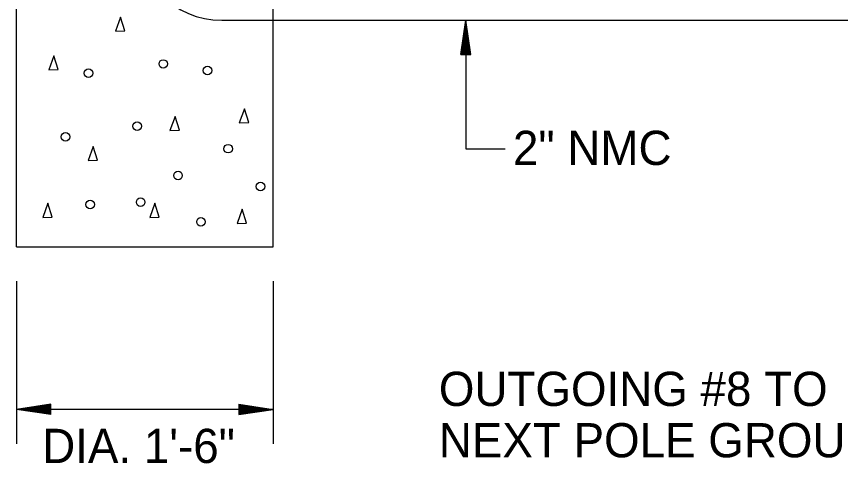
# Model space of a CAD drawing. Extents: x 1370050 to 1370716, y 380076 to 380502.
# Drawn here: x 1370124.1 to 1370196.4, y 380323.6 to 380362.8 of the extents above; entities that cross this region are included whole.
import ezdxf

# ---------------------------------------------------------------- set-up
doc = ezdxf.new("R2010")
doc.units = 0
doc.layers.add('R_Grid', color=7, linetype='Continuous')

msp = doc.modelspace()

# ---------------------------------------------------------------- linework, layer by layer
at = {"layer": 'R_Grid'}
for p, q in [((1370124.106, 380342.578), (1370124.106, 380387.578)), ((1370146.606, 380342.578), (1370146.606, 380387.578)), ((1370142.106, 380362.44), (1370216.311, 380362.44)), ((1370163.07, 380359.44), (1370163.52, 380362.44)), ((1370163.52, 380362.44), (1370163.52, 380351.167)), ((1370163.97, 380359.44), (1370163.52, 380362.44)), ((1370163.145, 380359.44), (1370163.52, 380361.939)), ((1370163.895, 380359.44), (1370163.52, 380361.939)), ((1370163.221, 380359.44), (1370163.52, 380361.423)), ((1370163.818, 380359.44), (1370163.52, 380361.423)), ((1370163.296, 380359.44), (1370163.52, 380360.924)), ((1370163.374, 380359.44), (1370163.52, 380360.415)), ((1370163.743, 380359.44), (1370163.52, 380360.924)), ((1370163.667, 380359.44), (1370163.52, 380360.415)), ((1370163.449, 380359.44), (1370163.52, 380359.914)), ((1370163.59, 380359.44), (1370163.52, 380359.914)), ((1370163.07, 380359.44), (1370163.97, 380359.44)), ((1370163.52, 380351.167), (1370166.976, 380351.167)), ((1370124.106, 380342.578), (1370146.606, 380342.578)), ((1370124.106, 380339.578), (1370124.106, 380325.328)), ((1370146.606, 380339.578), (1370146.606, 380325.328)), ((1370127.106, 380328.778), (1370124.106, 380328.328)), ((1370127.106, 380328.703), (1370124.607, 380328.328)), ((1370127.106, 380328.626), (1370125.123, 380328.328)), ((1370127.106, 380328.551), (1370125.623, 380328.328)), ((1370127.106, 380328.475), (1370126.131, 380328.328)), ((1370127.106, 380327.878), (1370127.106, 380328.778)), ((1370143.606, 380328.778), (1370146.606, 380328.328)), ((1370143.606, 380328.778), (1370143.606, 380327.878)), ((1370143.606, 380328.703), (1370146.105, 380328.328)), ((1370143.606, 380328.626), (1370145.589, 380328.328)), ((1370143.606, 380328.551), (1370145.09, 380328.328)), ((1370143.606, 380328.473), (1370144.581, 380328.328)), ((1370146.606, 380328.328), (1370124.106, 380328.328)), ((1370127.106, 380327.878), (1370124.106, 380328.328)), ((1370127.106, 380327.953), (1370124.607, 380328.328)), ((1370127.106, 380328.029), (1370125.123, 380328.328)), ((1370127.106, 380328.104), (1370125.623, 380328.328)), ((1370127.106, 380328.182), (1370126.131, 380328.328)), ((1370127.106, 380328.398), (1370126.632, 380328.328)), ((1370127.106, 380328.257), (1370126.632, 380328.328)), ((1370143.606, 380328.398), (1370144.08, 380328.328)), ((1370143.606, 380327.878), (1370146.606, 380328.328)), ((1370143.606, 380328.181), (1370144.581, 380328.328)), ((1370143.606, 380328.029), (1370145.589, 380328.328)), ((1370143.606, 380327.953), (1370146.105, 380328.328)), ((1370143.606, 380328.104), (1370145.09, 380328.328)), ((1370143.606, 380328.257), (1370144.08, 380328.328))]:
    msp.add_line(p, q, dxfattribs=at)
for points in [[(1370133.236, 380362.719), (1370132.783, 380361.474), (1370133.608, 380361.508), (1370133.236, 380362.719)], [(1370127.391, 380359.333), (1370126.937, 380358.088), (1370127.762, 380358.122), (1370127.391, 380359.333)], [(1370144.104, 380354.686), (1370143.65, 380353.441), (1370144.475, 380353.475), (1370144.104, 380354.686)], [(1370138.022, 380354.015), (1370137.568, 380352.77), (1370138.393, 380352.804), (1370138.022, 380354.015)], [(1370130.839, 380351.38), (1370130.385, 380350.135), (1370131.21, 380350.169), (1370130.839, 380351.38)], [(1370126.864, 380346.398), (1370126.411, 380345.153), (1370127.236, 380345.186), (1370126.864, 380346.398)], [(1370136.25, 380346.398), (1370135.796, 380345.153), (1370136.621, 380345.186), (1370136.25, 380346.398)], [(1370143.912, 380345.871), (1370143.458, 380344.626), (1370144.283, 380344.659), (1370143.912, 380345.871)]]:
    msp.add_lwpolyline(points, dxfattribs=at)
for centre in [(1370136.982, 380358.608), (1370130.428, 380357.807), (1370140.861, 380358.033), (1370134.684, 380353.147), (1370128.404, 380352.223), (1370142.681, 380351.182), (1370138.275, 380348.835), (1370145.506, 380347.877), (1370130.565, 380346.296), (1370134.998, 380346.501), (1370140.286, 380344.763)]:
    msp.add_circle(centre, 0.375, dxfattribs=at)
msp.add_arc((1370142.106, 380369.94), 7.5, 180, 270, dxfattribs=at)

# ---------------------------------------------------------------- texts
for s, height, p in [('2" NMC', 3, (1370167.653, 380349.753)), ('OUTGOING #8 TO', 2.99999, (1370161.151, 380328.633)), ('NEXT POLE GROUND', 2.99999, (1370161.151, 380324.133)), ('DIA. 1\'-6"', 3, (1370126.361, 380323.635))]:
    msp.add_text(s, height=height, dxfattribs=at).set_placement(p)

doc.saveas('drawing.dxf')
